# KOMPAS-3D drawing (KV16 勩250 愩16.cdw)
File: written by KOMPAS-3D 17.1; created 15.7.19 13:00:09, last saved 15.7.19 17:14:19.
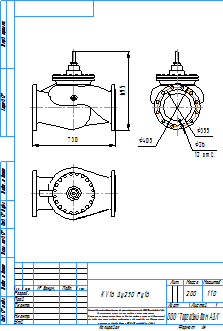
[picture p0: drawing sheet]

Sheet 1: A4, portrait

Title block, sheet 1: name: KV16 Ду250 Ру16; material: Сталь 20  ГОСТ 1050-2013; mass: 200; sheets: 1; sheet format: A4; stored path: C:\Users\kka\KOMPAS_Work\!Trash\KV16 ГРАНВЕНТ с эл.приводами\KV16 Ду250 Ру16.cdw

Views: Вид 1, Проекционный вид 2, Проекционный вид 3
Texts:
  kka
  adl
  Рама для чертежей
  Лит-Масса-Масштаб
  Материал-Предприятие
  Масштаб
  Изм.
  Лист
  № докум.
  Подп.
  Дата
  Лит.
  Разраб.
  Пров.
  Т.контр.
  Листов
  Внимание! Данный продукт является объектом авторского права ООО «Торговый Дом АДЛ».
  Запрещается изменение, копирование, распространение
  (в том числе путем копирования на другие сайты и ресурсы в Интернете)
  или любое иное использование информации и объектов без предварительного
  согласия правообладателя (ООО «Торговый Дом АДЛ»).
  Н.контр.
  Утв.
  ООО "Торговый дом АДЛ"
  Изменение
  Номер документа
  Подпись
  Обозначение документа
  Наименование изделия
  Масса изделия по ГОСТ 2.109-73
  Порядковый номер листа
  Общее количество листов в документе
  Характер работы, выполненной лицом, подписавшим документ
  Наименование или индекс предприятия, выпускающего документ
  Инв. № подл.
  Подп. и дата
  Взам. инв. №
  Инв. № дубл.
  Инвентарный номер подлинника по ГОСТ 2.501-68
  Подпись принявшего подлинник в отдел технической документации
  Инвентарный номер подлинника, взамен которого выпущен данный подлинник
  Инвентарный номер дубликата по ГОСТ 2.502-68
  Подпись принявшего дубликат в отдел технической документации
  Справ. №
  Перв. примен.
  Обозначение документа, взамен или на основании которого выпущен данный документ
  Обозначение документа, в котором впервые записан данный документ
  Подпись лица, копировавшего чертеж
  Обозначение формата листа
  !Рама для чертежа
Dimensions and other numbers on the sheet: 730; 695; 355; 405; 26; 12 отв.; 1:10; 1; 200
